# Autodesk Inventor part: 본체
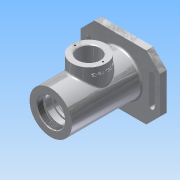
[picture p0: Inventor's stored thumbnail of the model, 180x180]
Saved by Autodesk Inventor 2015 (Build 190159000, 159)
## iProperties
Created: 2017-10
Part Number: 본체
Material: 알루미늄 6061
Document SubType Name: Modeling
Designer: Administrator
Density: 2.7 g/cm^3
Appearance: 알루미늄 - 평지
Author: Administrator
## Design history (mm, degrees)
sketch "스케치1"
  geometry: C1 r 31 at (0, 0); 1 further point
  constraints: 1 centre point, 1 coincident
  dimensions: "d0" = 62 diameter of C1
extrude "돌출1" new body sketch "스케치1" distance "d1" = 102; taper "d2" = 0 deg
sketch "스케치2"
  geometry: L1 (-58, 47)-(58, 47); L2 (58, 47)-(58, -47); L3 (58, -47)-(-58, -47); L4 (-58, -47)-(-58, 47); C1 r 31 at (0, 0) reference; 2 further points
  constraints: 8 end point, 2 midpoint, 2 parallel, 1 horizontal, 1 horizontal alignment, 1 perpendicular, 1 vertical alignment
  dimensions: "d3" = 94 distance of L1.end L2.end; "d4" = 116 distance of L2.end L3.end
extrude "돌출2" join sketch "스케치2" distance "d5" = 10; taper "d6" = 0 deg
sketch "스케치3"
  geometry: C1 r 35 at (0, 0); 1 further point
  constraints: 1 centre point, 1 coincident
  dimensions: "d7" = 70 diameter of C1
extrude "돌출3" join sketch "스케치3" distance "d8" = 3; taper "d9" = 0 deg
chamfer "모따기1" distance "d10" = 20; stored, may be unused: second distance "d11" = 2, angle "d12" = 45 deg
sketch "스케치4"
  geometry: L1 (-46, 20)-(-46, -20); L2 (-42, 20)-(-42, -20); L3 (-50, -20)-(-50, 20); C1 r 35 at (0, 0) reference; A1 r 4 centre (-46, 20) between (-42, 20) and (-50, 20); A2 r 4 centre (-46, -20) between (-50, -20) and (-42, -20); 1 further point
  constraints: 8 end point, 4 point on circle, 4 tangent, 2 centre point, 1 midpoint, 1 parallel, 1 vertical
  dimensions: "d13" = 40 distance of L1.start L1.end; "d14" = 20 vertical distance of L1.end C1.centre; "d15" = 46 distance from line of C1.centre L1; "d16" = 4 radius of A1
extrude "돌출4" cut sketch "스케치4" stored distance "d17" = 3; taper "d18" = 0 deg
node "작업 평면1"
sketch "스케치5"
  geometry: L1 (-31, -102)-(31, -102) reference; L2 (-31, 0)-(31, 0) reference; C1 r 25 at (0, -56); 2 further points
  constraints: 1 centre point, 1 midpoint, 1 vertical alignment
  dimensions: "d20" = 50 diameter of C1; "d21" = 56 distance from line of L2 C1.centre
extrude "돌출5" join sketch "스케치5" stored distance "d22" = 3; taper "d23" = 0 deg
sketch "스케치6"
  geometry: C1 r 31 at (0, 0) reference; 1 further point
  constraints: 1 coincident
hole "구멍1" sketch "스케치6" at (0, 0) diameter "d24" = 40.376; stored, may be unused: countersink angle "d28" = 90 deg, drill point angle "d30" = 118 deg; dims "d25" = 9, "d26" = 4, "d27" = 2, "d29" = 9
sketch "스케치7"
  geometry: L1 (35, -112)-(35, -115) reference; L2 (35, -115)-(-35, -115) reference; L3 (-35, -115)-(-35, -112) reference; L4 (-35, -112)-(-47, -112) reference; L5 (-47, -112)-(-47, -102) reference; L6 (-47, -102)-(-31, -102) reference; L7 (-31, -102)-(-31, 0) reference; L8 (-31, 0)-(-20.188, 0) reference; L9 (-20.188, 0)-(-20.188, -9) reference; L10 (-20.188, -9)-(0, -21.13) reference; L11 (0, -21.13)-(20.188, -9) reference; L12 (20.188, -9)-(20.188, 0) reference; L13 (20.188, 0)-(31, 0) reference; L14 (31, 0)-(31, -31) reference; L15 (31, -31)-(47, -31) reference; L16 (47, -31)-(47, -81) reference; L17 (47, -81)-(31, -81) reference; L18 (31, -81)-(31, -102) reference; L19 (31, -102)-(47, -102) reference; L20 (47, -102)-(47, -112) reference; L21 (47, -112)-(35, -112) reference; L22 (0, 45)-(0, -188); L23 (0, -9)-(24, -9); L24 (24, -9)-(24, -12); L25 (24, -12)-(20, -12); L26 (20, -12)-(20, -21); L27 (20, -21)-(17.5, -21); L28 (17.5, -21)-(17.5, -24.25); L29 (17.5, -24.25)-(18.5, -24.25); L30 (18.5, -24.25)-(18.5, -26); L31 (18.5, -26)-(17.5, -26); L32 (17.5, -26)-(17.5, -37); L33 (17.5, -37)-(26, -37); L34 (26, -37)-(26, -75); L35 (26, -75)-(17.5, -75); L36 (17.5, -75)-(17.5, -86); L37 (17.5, -86)-(16.5, -86); L38 (16.5, -86)-(16.5, -91); L39 (16.5, -91)-(10, -91); L40 (10, -91)-(10, -93.7); L41 (10, -93.7)-(12.5, -93.7); L42 (12.5, -93.7)-(12.5, -100.3); L43 (12.5, -100.3)-(12.904, -101); L44 (12.904, -101)-(16, -101); L45 (16, -101)-(22, -115); L46 (22, -115)-(0, -115); L47 (0, -115)-(0, -9); 1 further point
  constraints: 52 end point, 10 horizontal, 8 vertical, 7 point on line, 4 perpendicular, 1 collinear, 1 midpoint
  dimensions: "d31" = 48 diameter of L23.end L22; "d32" = 3 distance of L23.end L24.end; "d33" = 40 diameter of L26 L22; "d34" = 21 distance from line of L26.end L13; "d35" = 35 diameter of L28 L22; "d36" = 37 diameter of L30 L22; "d37" = 1.75 distance of L29.end L30.end; "d39" = 26 distance between parallel lines of L13 L31; "d40" = 11 distance of L31.end L32.end; "d41" = 52 diameter of L33.end L22; "d42" = 38 distance of L33.end L34.end; "d43" = 60 vertical distance of L30.end L36.end; "d44" = 33 diameter of L37.end L22; "d45" = 5 distance of L37.end L38.end; "d46" = 20 diameter of L39.end L22; "d47" = 2.7 distance of L39.end L40.end; "d48" = 25 diameter of L41.end L22; "d49" = 6.6 distance of L41.end L42.end; "d50" = 30 deg angle of L42 L43; "d51" = 0.7 vertical distance of L42.end L43.end; "d52" = 32 diameter of L44.end L22; "d53" = 44 diameter of L45.end L22
revolve "회전1" sketch "스케치7" stored, may be unused: angle "d54" = 90 deg
fillet "모깎기1" dims "d55" = 3
fillet "모깎기2" dims "d56" = 3
fillet "모깎기3" dims "d57" = 0.3
fillet "모깎기4" dims "d58" = 3
fillet "모깎기5" dims "d59" = 0.3
fillet "모깎기6" dims "d60" = 3
fillet "모깎기7" dims "d61" = 3
chamfer "모따기2" distance "d62" = 1; stored, may be unused: second distance "d63" = 2, angle "d64" = 45 deg
sketch "스케치8"
  geometry: C1 r 25 at (0, 0) reference; C2 r 16 at (0, 0); 1 further point
  constraints: 1 centre point, 1 coincident
  dimensions: "d65" = 32 diameter of C2
extrude "돌출6" cut sketch "스케치8" stored distance "d66" = 3; taper "d67" = 0 deg
sketch "스케치9"
  geometry: C1 r 25 at (0, 0) reference; A1 r 20.5 centre (0, 0) between (-20.5, 0) and (20.5, 0); 1 further point
  constraints: 2 point on circle, 1 centre point, 1 coincident
  dimensions: "d68" = 41 diameter of A1
hole "구멍2" sketch "스케치9" at (-20.5, 0), (20.5, 0) diameter "d69" = 2.459; stored, may be unused: countersink angle "d73" = 90 deg, drill point angle "d75" = 118 deg; dims "d70" = 6, "d71" = 4, "d72" = 2, "d74" = 8
node "작업 평면2"
sketch "스케치10"
  geometry: L1 (42, -38.5)-(42, -73.5); L2 (42, -73.5)-(32, -73.5); L3 (32, -73.5)-(32, -38.5); L4 (32, -38.5)-(42, -38.5); L5 (-31, 0)-(31, 0) reference; L6 (47, -31)-(47, -81) reference; 4 further points
  constraints: 2 midpoint, 1 horizontal alignment, 1 vertical alignment, 2 other
  dimensions: "d77" = 35 distance of L1.start L1.end; "d78" = 10 distance of L1.end L2.end; "d79" = 56 distance from line of L5 point (37, -56); "d80" = 10 distance from line of point (37, -56) L6
feature "엠보싱1" sketch "스케치10" dims "d2" = 0, "d81" = 0.5, "d82" = 0
chamfer "모따기3" distance "d83" = 1; stored, may be unused: second distance "d84" = 2, angle "d85" = 45 deg
chamfer "모따기4" distance "d86" = 1; stored, may be unused: second distance "d87" = 2, angle "d88" = 45 deg
chamfer "모따기5" distance "d89" = 1; stored, may be unused: second distance "d90" = 2, angle "d91" = 45 deg
node "솔리드1"
mirror "대칭1"
node "투영된 루프1"
node "절단 모서리 투영1"
other parameters: "d19" = 47, "d76" = 36.25
